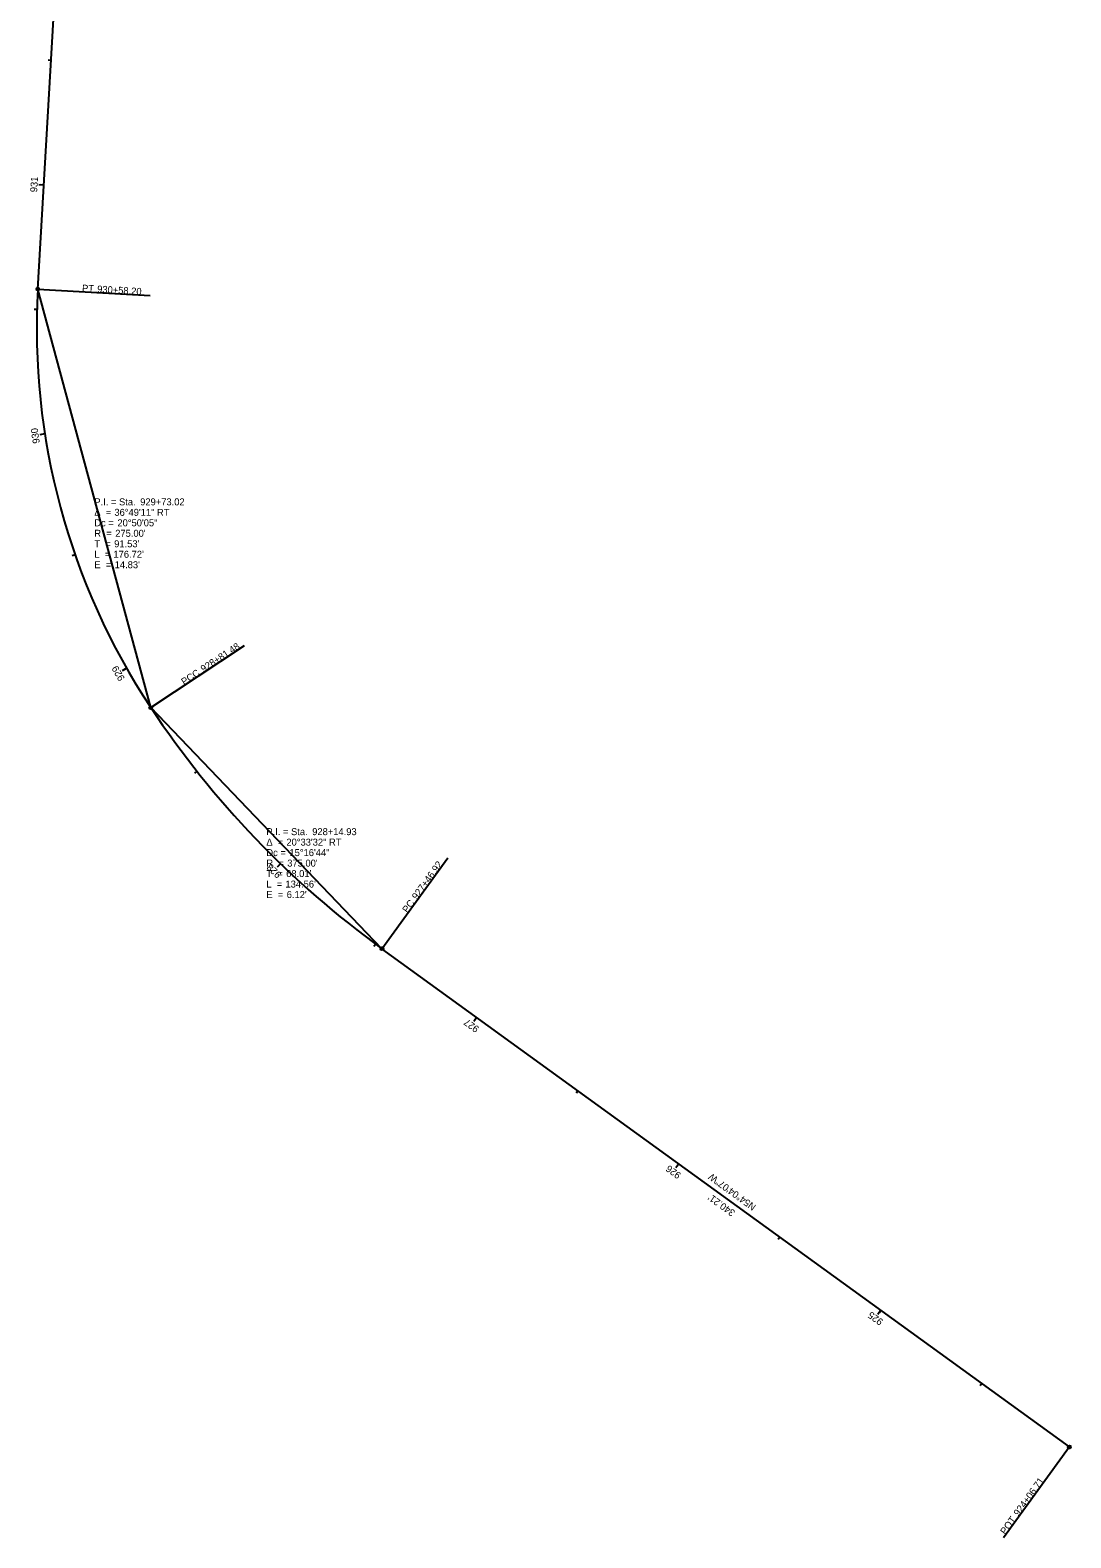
# Model space of a CAD drawing. Extents: x 1978725 to 1979446, y 230316 to 232755.
# Drawn here: x 1978745 to 1979162, y 230316 to 230920 of the extents above; entities that cross this region are included whole.
import ezdxf

# ---------------------------------------------------------------- set-up
doc = ezdxf.new("R2010")
doc.units = 0
for name, color, linetype in [('GE_X_Alignment', 7, 'Continuous'), ('GE_X_Alignment_1000_Curve_Data', 7, 'Continuous'), ('GE_X_Alignment_1000_Stations', 7, 'Continuous'), ('GE_X_Alignment_100_Curve_Data', 7, 'Continuous'), ('GE_X_Alignment_100_Stations', 7, 'Continuous'), ('GE_X_Alignment_500_Curve_Data', 7, 'Continuous'), ('GE_X_Alignment_500_Stations', 7, 'Continuous'), ('SC_Scratch1', 7, 'Continuous')]:
    doc.layers.add(name, color=color, linetype=linetype)

msp = doc.modelspace()

# ---------------------------------------------------------------- linework, layer by layer
at = {"layer": 'GE_X_Alignment'}
for p, q in [((1978747.86, 230816.18), (1978770.14, 231201.33)), ((1979161.2, 230352.22), (1978885.73, 230551.86))]:
    msp.add_line(p, q, dxfattribs=at)
for centre, radius, start, end in [((1979022.4, 230800.3), 275, 176.68999, 213.50971), ((1979105.78, 230855.51), 375, 213.50971, 234.06873)]:
    msp.add_arc(centre, radius, start, end, dxfattribs=at)
at = {"layer": 'GE_X_Alignment_1000_Stations'}
for p, q in [((1978747.86, 230816.18), (1978792.79, 230813.58)), ((1978750.65, 230758.15), (1978748.68, 230757.84)), ((1978793.11, 230648.48), (1978830.63, 230673.32)), ((1978885.73, 230551.86), (1978912.13, 230588.3)), ((1979085.67, 230406.96), (1979084.96, 230405.99)), ((1979161.2, 230352.22), (1979134.8, 230315.78))]:
    msp.add_line(p, q, dxfattribs=at)
for centre in [(1978747.86, 230816.18), (1978793.11, 230648.48), (1978885.73, 230551.86), (1979161.2, 230352.22)]:
    msp.add_circle(centre, 0.6, dxfattribs=at)
at = {"layer": 'GE_X_Alignment_100_Stations'}
for p, q in [((1978753.16, 230907.82), (1978751.96, 230907.89)), ((1978750.27, 230857.9), (1978748.28, 230858.02)), ((1978747.86, 230816.18), (1978792.79, 230813.58)), ((1978747.51, 230807.98), (1978746.31, 230808.01)), ((1978750.65, 230758.15), (1978748.68, 230757.84)), ((1978762.75, 230709.71), (1978761.62, 230709.31)), ((1978793.11, 230648.48), (1978830.63, 230673.32)), ((1978783.41, 230664.25), (1978781.68, 230663.26)), ((1978811.57, 230622.99), (1978810.63, 230622.24)), ((1978845.09, 230585.94), (1978843.7, 230584.5)), ((1978885.73, 230551.86), (1978912.13, 230588.3)), ((1978883.24, 230553.68), (1978882.53, 230552.71)), ((1978923.72, 230524.33), (1978922.55, 230522.71)), ((1978964.21, 230494.99), (1978963.5, 230494.01)), ((1979004.69, 230465.64), (1979003.52, 230464.03)), ((1979045.18, 230436.3), (1979044.48, 230435.33)), ((1979085.67, 230406.96), (1979084.49, 230405.34)), ((1979126.15, 230377.62), (1979125.45, 230376.65)), ((1979161.2, 230352.22), (1979134.8, 230315.78))]:
    msp.add_line(p, q, dxfattribs=at)
for centre in [(1978747.86, 230816.18), (1978793.11, 230648.48), (1978885.73, 230551.86), (1979161.2, 230352.22)]:
    msp.add_circle(centre, 0.6, dxfattribs=at)
at = {"layer": 'GE_X_Alignment_500_Stations'}
for p, q in [((1978750.27, 230857.9), (1978749.08, 230857.97)), ((1978747.86, 230816.18), (1978792.79, 230813.58)), ((1978750.65, 230758.15), (1978748.68, 230757.84)), ((1978793.11, 230648.48), (1978830.63, 230673.32)), ((1978783.41, 230664.25), (1978782.37, 230663.66)), ((1978845.09, 230585.94), (1978844.26, 230585.08)), ((1978885.73, 230551.86), (1978912.13, 230588.3)), ((1978923.72, 230524.33), (1978923.02, 230523.35)), ((1979004.69, 230465.64), (1979003.99, 230464.67)), ((1979085.67, 230406.96), (1979084.49, 230405.34)), ((1979161.2, 230352.22), (1979134.8, 230315.78))]:
    msp.add_line(p, q, dxfattribs=at)
for centre in [(1978747.86, 230816.18), (1978793.11, 230648.48), (1978885.73, 230551.86), (1979161.2, 230352.22)]:
    msp.add_circle(centre, 0.6, dxfattribs=at)
at = {"layer": 'SC_Scratch1'}
for p, q in [((1978793.11, 230648.48), (1978747.86, 230816.18)), ((1978885.73, 230551.86), (1978793.11, 230648.48))]:
    msp.add_line(p, q, dxfattribs=at)

# ---------------------------------------------------------------- texts
at = {"layer": 'GE_X_Alignment_1000_Curve_Data'}
for s, p in [('Δ  = ', (1978770.48, 230725.33)), ('P.I. = Sta. ', (1978770.48, 230729.53)), ('36°49\'11" RT', (1978778.51, 230725.33)), ('929+73.02', (1978788.85, 230729.53)), ('Dc = ', (1978770.48, 230721.13)), ('20°50\'05"', (1978779.72, 230721.13)), ('R  = ', (1978770.48, 230716.93)), ("275.00'", (1978778.85, 230716.93)), ('T  = ', (1978770.48, 230712.73)), ('L  = ', (1978770.48, 230708.53)), ("176.72'", (1978778.13, 230708.53)), ("91.53'", (1978778.42, 230712.73)), ('E  = ', (1978770.48, 230704.33)), ("14.83'", (1978778.64, 230704.33)), ('Δ  = ', (1978839.42, 230593.17)), ('P.I. = Sta. ', (1978839.42, 230597.37)), ('20°33\'32" RT', (1978847.44, 230593.17)), ('928+14.93', (1978857.79, 230597.37)), ('Dc = ', (1978839.42, 230588.97)), ('15°16\'44"', (1978848.66, 230588.97)), ('T  = ', (1978839.42, 230580.57)), ('R  = ', (1978839.42, 230584.77)), ("68.01'", (1978847.35, 230580.57)), ("375.00'", (1978847.79, 230584.77)), ('L  = ', (1978839.42, 230576.37)), ("134.56'", (1978847.06, 230576.37)), ('E  = ', (1978839.42, 230572.17)), ("6.12'", (1978847.57, 230572.17))]:
    msp.add_text(s, height=2.8, dxfattribs=at).set_placement(p)
at = {"layer": 'GE_X_Alignment_1000_Stations'}
for s, rotation, p in [('PT', 356.68999, (1978765.48, 230815.21)), ('930+58.20', 356.68999, (1978771.55, 230814.85)), ('930', 98.81683, (1978748.64, 230754.52)), ('928+81.48', 33.50971, (1978814.23, 230662.52)), ('PCC', 33.50971, (1978806.44, 230657.36)), ('927+46.92', 54.06873, (1978899.74, 230571.28)), ('PC', 54.06873, (1978895.92, 230566)), ('N54°04\'07"W', 144.06873, (1979035.89, 230448.96)), ("340.21'", 144.06873, (1979027.54, 230446.62)), ('924+06.71', 54.06873, (1979140.87, 230324.25)), ('POT', 54.06873, (1979135.52, 230316.85))]:
    msp.add_text(s, height=2.8, rotation=rotation, dxfattribs=at).set_placement(p)
at = {"layer": 'GE_X_Alignment_100_Curve_Data'}
for s, p in [('Δ  = ', (1978770.48, 230725.33)), ('P.I. = Sta. ', (1978770.48, 230729.53)), ('36°49\'11" RT', (1978778.51, 230725.33)), ('929+73.02', (1978788.85, 230729.53)), ('Dc = ', (1978770.48, 230721.13)), ('20°50\'05"', (1978779.72, 230721.13)), ('R  = ', (1978770.48, 230716.93)), ("275.00'", (1978778.85, 230716.93)), ('T  = ', (1978770.48, 230712.73)), ('L  = ', (1978770.48, 230708.53)), ("176.72'", (1978778.13, 230708.53)), ("91.53'", (1978778.42, 230712.73)), ('E  = ', (1978770.48, 230704.33)), ("14.83'", (1978778.64, 230704.33)), ('Δ  = ', (1978839.42, 230593.17)), ('P.I. = Sta. ', (1978839.42, 230597.37)), ('20°33\'32" RT', (1978847.44, 230593.17)), ('928+14.93', (1978857.79, 230597.37)), ('Dc = ', (1978839.42, 230588.97)), ('15°16\'44"', (1978848.66, 230588.97)), ('T  = ', (1978839.42, 230580.57)), ('R  = ', (1978839.42, 230584.77)), ("68.01'", (1978847.35, 230580.57)), ("375.00'", (1978847.79, 230584.77)), ('L  = ', (1978839.42, 230576.37)), ("134.56'", (1978847.06, 230576.37)), ('E  = ', (1978839.42, 230572.17)), ("6.12'", (1978847.57, 230572.17))]:
    msp.add_text(s, height=2.8, dxfattribs=at).set_placement(p)
at = {"layer": 'GE_X_Alignment_100_Stations'}
for s, rotation, p in [('931', 86.68999, (1978747.55, 230854.94)), ('PT', 356.68999, (1978765.48, 230815.21)), ('930+58.20', 356.68999, (1978771.55, 230814.85)), ('930', 98.81683, (1978748.64, 230754.52)), ('928+81.48', 33.50971, (1978814.23, 230662.52)), ('929', 119.65166, (1978782.81, 230660.16)), ('PCC', 33.50971, (1978806.44, 230657.36)), ('928', 135.95935, (1978845.68, 230581.83)), ('927+46.92', 54.06873, (1978899.74, 230571.28)), ('PC', 54.06873, (1978895.92, 230566)), ('927', 144.06873, (1978924.93, 230520.3)), ('926', 144.06873, (1979005.86, 230461.65)), ('N54°04\'07"W', 144.06873, (1979035.89, 230448.96)), ("340.21'", 144.06873, (1979027.54, 230446.62)), ('925', 144.06873, (1979086.84, 230402.97)), ('924+06.71', 54.06873, (1979140.87, 230324.25)), ('POT', 54.06873, (1979135.52, 230316.85))]:
    msp.add_text(s, height=2.8, rotation=rotation, dxfattribs=at).set_placement(p)
at = {"layer": 'GE_X_Alignment_500_Curve_Data'}
for s, p in [('Δ  = ', (1978770.48, 230725.33)), ('P.I. = Sta. ', (1978770.48, 230729.53)), ('36°49\'11" RT', (1978778.51, 230725.33)), ('929+73.02', (1978788.85, 230729.53)), ('Dc = ', (1978770.48, 230721.13)), ('20°50\'05"', (1978779.72, 230721.13)), ('R  = ', (1978770.48, 230716.93)), ("275.00'", (1978778.85, 230716.93)), ('T  = ', (1978770.48, 230712.73)), ('L  = ', (1978770.48, 230708.53)), ("176.72'", (1978778.13, 230708.53)), ("91.53'", (1978778.42, 230712.73)), ('E  = ', (1978770.48, 230704.33)), ("14.83'", (1978778.64, 230704.33)), ('Δ  = ', (1978839.42, 230593.17)), ('P.I. = Sta. ', (1978839.42, 230597.37)), ('20°33\'32" RT', (1978847.44, 230593.17)), ('928+14.93', (1978857.79, 230597.37)), ('Dc = ', (1978839.42, 230588.97)), ('15°16\'44"', (1978848.66, 230588.97)), ('T  = ', (1978839.42, 230580.57)), ('R  = ', (1978839.42, 230584.77)), ("68.01'", (1978847.35, 230580.57)), ("375.00'", (1978847.79, 230584.77)), ('L  = ', (1978839.42, 230576.37)), ("134.56'", (1978847.06, 230576.37)), ('E  = ', (1978839.42, 230572.17)), ("6.12'", (1978847.57, 230572.17))]:
    msp.add_text(s, height=2.8, dxfattribs=at).set_placement(p)
at = {"layer": 'GE_X_Alignment_500_Stations'}
for s, rotation, p in [('PT', 356.68999, (1978765.48, 230815.21)), ('930+58.20', 356.68999, (1978771.55, 230814.85)), ('930', 98.81683, (1978748.64, 230754.52)), ('928+81.48', 33.50971, (1978814.23, 230662.52)), ('PCC', 33.50971, (1978806.44, 230657.36)), ('927+46.92', 54.06873, (1978899.74, 230571.28)), ('PC', 54.06873, (1978895.92, 230566)), ('N54°04\'07"W', 144.06873, (1979035.89, 230448.96)), ("340.21'", 144.06873, (1979027.54, 230446.62)), ('925', 144.06873, (1979086.84, 230402.97)), ('924+06.71', 54.06873, (1979140.87, 230324.25)), ('POT', 54.06873, (1979135.52, 230316.85))]:
    msp.add_text(s, height=2.8, rotation=rotation, dxfattribs=at).set_placement(p)

doc.saveas('drawing.dxf')
